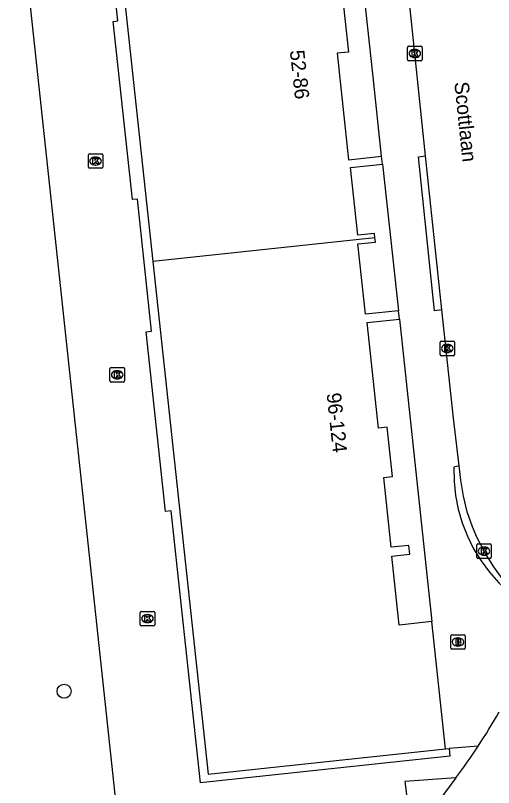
# Model space of a CAD drawing. Extents: x 161253 to 161848, y 384872 to 385383.
# Drawn here: x 161322.6 to 161355.7, y 384938.3 to 384991.8 of the extents above; entities that cross this region are included whole.
import ezdxf

# ---------------------------------------------------------------- set-up
doc = ezdxf.new("R2010")
doc.units = 0
for name, color, linetype in [('IMGEO_Boom', 7, 'Continuous'), ('IMGEO_Brandkraan', 7, 'Continuous'), ('IMGEO_Fietspad_gesloten', 7, 'Continuous'), ('IMGEO_Kolk', 7, 'Continuous'), ('IMGEO_Openbare_ruimte_label', 7, 'Continuous'), ('IMGEO_Pand', 7, 'Continuous'), ('IMGEO_Pand_nummerreeks', 7, 'Continuous'), ('IMGEO_Rijbaan_lokaal_open', 7, 'Continuous'), ('IMGEO_Voetpad_open', 7, 'Continuous')]:
    doc.layers.add(name, color=color, linetype=linetype)

msp = doc.modelspace()

# ---------------------------------------------------------------- linework, layer by layer
at = {"layer": 'IMGEO_Boom'}
msp.add_circle((161325.944, 384945.018), 0.489, dxfattribs=at)
at = {"layer": 'IMGEO_Brandkraan'}
for p, q in [((161352.707, 384948), (161352.707, 384948.852)), ((161352.782, 384948.926), (161353.634, 384948.926)), ((161353.708, 384948.852), (161353.708, 384948)), ((161353.195, 384948.706), (161353.22, 384948.706)), ((161353.634, 384947.926), (161352.782, 384947.926)), ((161353.218, 384948.146), (161353.193, 384948.146))]:
    msp.add_line(p, q, dxfattribs=at)
for points in [[(161352.707, 384948), (161352.707, 384948.852)], [(161352.782, 384948.926), (161353.634, 384948.926)], [(161353.708, 384948.852), (161353.708, 384948)], [(161353.055, 384948.626), (161353.055, 384948.226), (161353.268, 384948.226)], [(161353.286, 384948.626), (161353.055, 384948.626)], [(161353.234, 384948.545), (161353.18, 384948.545), (161353.18, 384948.469)], [(161353.18, 384948.469), (161353.233, 384948.469)], [(161353.242, 384948.393), (161353.18, 384948.393), (161353.18, 384948.312)], [(161353.18, 384948.312), (161353.242, 384948.312)], [(161353.634, 384947.926), (161352.782, 384947.926)]]:
    msp.add_lwpolyline(points, dxfattribs=at)
for centre, radius, start, end in [((161352.784, 384948.85), 0.0765, 91.552, 178.448), ((161352.784, 384948.85), 0.0765, 91.552, 178.448), ((161353.632, 384948.85), 0.0765, 1.552, 88.448), ((161353.632, 384948.85), 0.0765, 1.552, 88.448), ((161353.235, 384948.507), 0.0379, 267.8285, 90.9355), ((161353.243, 384948.352), 0.0404, 269.8759, 90.5077), ((161353.274, 384948.477), 0.251, 268.6676, 293.5347), ((161353.29, 384948.481), 0.145, 59.4692, 91.5367), ((161353.315, 384948.528), 0.0922, 285.5137, 58.1501), ((161353.32, 384948.336), 0.105, 301.3115, 78.989), ((161352.784, 384948.002), 0.0765, 181.552, 268.448), ((161352.784, 384948.002), 0.0765, 181.552, 268.448), ((161353.632, 384948.002), 0.0765, 271.552, 358.448), ((161353.632, 384948.002), 0.0765, 271.552, 358.448)]:
    msp.add_arc(centre, radius, start, end, dxfattribs=at)
for centre, major_axis, ratio, start_param, end_param in [((161353.194, 384948.426), (-0.387, 0.002), 0.722429, 4.712389, 7.853982), ((161353.219, 384948.426), (-0.39, 0.002), 0.717154, 1.570796, 4.712389)]:
    msp.add_ellipse(centre, major_axis=major_axis, ratio=ratio, start_param=start_param, end_param=end_param, dxfattribs=at)
at = {"layer": 'IMGEO_Fietspad_gesloten'}
msp.add_lwpolyline([(161353.067, 384939.032), (161352.732, 384938.592), (161341.413, 384923.282)], dxfattribs=at)
msp.add_arc((161318.363, 384965.194), 43.457, 326.5147, 330.1784, dxfattribs=at)
at = {"layer": 'IMGEO_Kolk'}
for p, q in [((161349.718, 384988.745), (161349.718, 384989.597)), ((161349.793, 384989.671), (161350.645, 384989.671)), ((161350.206, 384989.451), (161350.231, 384989.451)), ((161350.719, 384989.597), (161350.719, 384988.745)), ((161350.229, 384988.891), (161350.204, 384988.891)), ((161350.645, 384988.671), (161349.793, 384988.671)), ((161327.62, 384981.296), (161327.62, 384982.148)), ((161327.695, 384982.222), (161328.547, 384982.222)), ((161328.108, 384982.002), (161328.133, 384982.002)), ((161328.621, 384982.148), (161328.621, 384981.296)), ((161328.131, 384981.442), (161328.106, 384981.442)), ((161328.547, 384981.222), (161327.695, 384981.222)), ((161351.968, 384968.323), (161351.968, 384969.175)), ((161352.043, 384969.249), (161352.895, 384969.249)), ((161352.969, 384969.175), (161352.969, 384968.323)), ((161352.456, 384969.029), (161352.481, 384969.029)), ((161352.895, 384968.249), (161352.043, 384968.249)), ((161352.479, 384968.469), (161352.454, 384968.469)), ((161329.119, 384966.5), (161329.119, 384967.352)), ((161329.194, 384967.426), (161330.046, 384967.426)), ((161329.607, 384967.206), (161329.632, 384967.206)), ((161330.12, 384967.352), (161330.12, 384966.5)), ((161330.046, 384966.426), (161329.194, 384966.426)), ((161329.63, 384966.646), (161329.605, 384966.646)), ((161354.51, 384954.293), (161354.51, 384955.145)), ((161354.585, 384955.219), (161355.437, 384955.219)), ((161355.511, 384955.145), (161355.511, 384954.293)), ((161354.998, 384954.999), (161355.023, 384954.999)), ((161355.437, 384954.219), (161354.585, 384954.219)), ((161355.021, 384954.439), (161354.996, 384954.439)), ((161331.213, 384949.622), (161331.213, 384950.474)), ((161331.288, 384950.548), (161332.14, 384950.548)), ((161332.214, 384950.474), (161332.214, 384949.622)), ((161331.701, 384950.328), (161331.726, 384950.328)), ((161332.14, 384949.548), (161331.288, 384949.548)), ((161331.724, 384949.768), (161331.699, 384949.768))]:
    msp.add_line(p, q, dxfattribs=at)
for points in [[(161349.718, 384988.745), (161349.718, 384989.597)], [(161349.793, 384989.671), (161350.645, 384989.671)], [(161350.039, 384989.371), (161350.162, 384989.371), (161350.162, 384989.22), (161350.292, 384989.371), (161350.456, 384989.371), (161350.31, 384989.22), (161350.463, 384988.971), (161350.311, 384988.971), (161350.226, 384989.135), (161350.162, 384989.068), (161350.162, 384988.971), (161350.039, 384988.971), (161350.039, 384989.371)], [(161350.719, 384989.597), (161350.719, 384988.745)], [(161350.645, 384988.671), (161349.793, 384988.671)], [(161327.62, 384981.296), (161327.62, 384982.148)], [(161327.695, 384982.222), (161328.547, 384982.222)], [(161327.941, 384981.922), (161328.064, 384981.922), (161328.064, 384981.771), (161328.194, 384981.922), (161328.358, 384981.922), (161328.212, 384981.771), (161328.365, 384981.522), (161328.213, 384981.522), (161328.128, 384981.686), (161328.064, 384981.619), (161328.064, 384981.522), (161327.941, 384981.522), (161327.941, 384981.922)], [(161328.621, 384982.148), (161328.621, 384981.296)], [(161328.547, 384981.222), (161327.695, 384981.222)], [(161351.968, 384968.323), (161351.968, 384969.175)], [(161352.043, 384969.249), (161352.895, 384969.249)], [(161352.969, 384969.175), (161352.969, 384968.323)], [(161352.289, 384968.949), (161352.412, 384968.949), (161352.412, 384968.798), (161352.542, 384968.949), (161352.706, 384968.949), (161352.56, 384968.798), (161352.713, 384968.549), (161352.561, 384968.549), (161352.476, 384968.713), (161352.412, 384968.646), (161352.412, 384968.549), (161352.289, 384968.549), (161352.289, 384968.949)], [(161352.895, 384968.249), (161352.043, 384968.249)], [(161329.119, 384966.5), (161329.119, 384967.352)], [(161329.194, 384967.426), (161330.046, 384967.426)], [(161329.44, 384967.126), (161329.563, 384967.126), (161329.563, 384966.975), (161329.693, 384967.126), (161329.857, 384967.126), (161329.711, 384966.975), (161329.864, 384966.726), (161329.712, 384966.726), (161329.627, 384966.89), (161329.563, 384966.823), (161329.563, 384966.726), (161329.44, 384966.726), (161329.44, 384967.126)], [(161330.12, 384967.352), (161330.12, 384966.5)], [(161330.046, 384966.426), (161329.194, 384966.426)], [(161354.51, 384954.293), (161354.51, 384955.145)], [(161354.585, 384955.219), (161355.437, 384955.219)], [(161355.511, 384955.145), (161355.511, 384954.293)], [(161354.831, 384954.919), (161354.954, 384954.919), (161354.954, 384954.768), (161355.084, 384954.919), (161355.248, 384954.919), (161355.102, 384954.768), (161355.255, 384954.519), (161355.103, 384954.519), (161355.018, 384954.683), (161354.954, 384954.616), (161354.954, 384954.519), (161354.831, 384954.519), (161354.831, 384954.919)], [(161355.437, 384954.219), (161354.585, 384954.219)], [(161331.213, 384949.622), (161331.213, 384950.474)], [(161331.288, 384950.548), (161332.14, 384950.548)], [(161332.214, 384950.474), (161332.214, 384949.622)], [(161331.534, 384950.248), (161331.657, 384950.248), (161331.657, 384950.097), (161331.787, 384950.248), (161331.951, 384950.248), (161331.805, 384950.097), (161331.958, 384949.848), (161331.806, 384949.848), (161331.721, 384950.012), (161331.657, 384949.945), (161331.657, 384949.848), (161331.534, 384949.848), (161331.534, 384950.248)], [(161332.14, 384949.548), (161331.288, 384949.548)]]:
    msp.add_lwpolyline(points, dxfattribs=at)
for centre, start, end in [((161349.795, 384989.595), 91.552, 178.448), ((161349.795, 384989.595), 91.552, 178.448), ((161350.643, 384989.595), 1.552, 88.448), ((161350.643, 384989.595), 1.552, 88.448), ((161349.795, 384988.747), 181.552, 268.448), ((161349.795, 384988.747), 181.552, 268.448), ((161350.643, 384988.747), 271.552, 358.448), ((161350.643, 384988.747), 271.552, 358.448), ((161327.697, 384982.146), 91.552, 178.448), ((161327.697, 384982.146), 91.552, 178.448), ((161328.545, 384982.146), 1.552, 88.448), ((161328.545, 384982.146), 1.552, 88.448), ((161327.697, 384981.298), 181.552, 268.448), ((161327.697, 384981.298), 181.552, 268.448), ((161328.545, 384981.298), 271.552, 358.448), ((161328.545, 384981.298), 271.552, 358.448), ((161352.045, 384969.173), 91.552, 178.448), ((161352.045, 384969.173), 91.552, 178.448), ((161352.893, 384969.173), 1.552, 88.448), ((161352.893, 384969.173), 1.552, 88.448), ((161352.045, 384968.325), 181.552, 268.448), ((161352.045, 384968.325), 181.552, 268.448), ((161352.893, 384968.325), 271.552, 358.448), ((161352.893, 384968.325), 271.552, 358.448), ((161329.196, 384967.35), 91.552, 178.448), ((161329.196, 384967.35), 91.552, 178.448), ((161330.044, 384967.35), 1.552, 88.448), ((161330.044, 384967.35), 1.552, 88.448), ((161329.196, 384966.502), 181.552, 268.448), ((161329.196, 384966.502), 181.552, 268.448), ((161330.044, 384966.502), 271.552, 358.448), ((161330.044, 384966.502), 271.552, 358.448), ((161354.587, 384955.143), 91.552, 178.448), ((161354.587, 384955.143), 91.552, 178.448), ((161355.435, 384955.143), 1.552, 88.448), ((161355.435, 384955.143), 1.552, 88.448), ((161354.587, 384954.295), 181.552, 268.448), ((161354.587, 384954.295), 181.552, 268.448), ((161355.435, 384954.295), 271.552, 358.448), ((161355.435, 384954.295), 271.552, 358.448), ((161331.29, 384950.472), 91.552, 178.448), ((161331.29, 384950.472), 91.552, 178.448), ((161332.138, 384950.472), 1.552, 88.448), ((161332.138, 384950.472), 1.552, 88.448), ((161331.29, 384949.624), 181.552, 268.448), ((161331.29, 384949.624), 181.552, 268.448), ((161332.138, 384949.624), 271.552, 358.448), ((161332.138, 384949.624), 271.552, 358.448)]:
    msp.add_arc(centre, 0.0765, start, end, dxfattribs=at)
for centre, major_axis, ratio, start_param, end_param in [((161350.205, 384989.171), (-0.387, 0.002), 0.722429, 4.712389, 7.853982), ((161350.23, 384989.171), (-0.39, 0.002), 0.717154, 1.570796, 4.712389), ((161328.107, 384981.722), (-0.387, 0.002), 0.722429, 4.712389, 7.853982), ((161328.132, 384981.722), (-0.39, 0.002), 0.717154, 1.570796, 4.712389), ((161352.455, 384968.749), (-0.387, 0.002), 0.722429, 4.712389, 7.853982), ((161352.48, 384968.749), (-0.39, 0.002), 0.717154, 1.570796, 4.712389), ((161329.606, 384966.926), (-0.387, 0.002), 0.722429, 4.712389, 7.853982), ((161329.631, 384966.926), (-0.39, 0.002), 0.717154, 1.570796, 4.712389), ((161354.997, 384954.719), (-0.387, 0.002), 0.722429, 4.712389, 7.853982), ((161355.022, 384954.719), (-0.39, 0.002), 0.717154, 1.570796, 4.712389), ((161331.7, 384950.048), (-0.387, 0.002), 0.722429, 4.712389, 7.853982), ((161331.725, 384950.048), (-0.39, 0.002), 0.717154, 1.570796, 4.712389)]:
    msp.add_ellipse(centre, major_axis=major_axis, ratio=ratio, start_param=start_param, end_param=end_param, dxfattribs=at)
at = {"layer": 'IMGEO_Pand'}
for points in [[(161345.188, 384997.822), (161345.22, 384997.527), (161343.986, 384997.395), (161344.504, 384992.575), (161345.261, 384992.657), (161345.626, 384989.268), (161344.847, 384989.184), (161345.639, 384981.819), (161347.916, 384982.064)], [(161329.788, 384996.166), (161332.09, 384974.761)], [(161347.976, 384981.513), (161347.916, 384982.064)], [(161347.464, 384976.414), (161347.432, 384976.709), (161346.267, 384976.583), (161345.763, 384981.275), (161347.976, 384981.513)], [(161347.464, 384976.414), (161332.09, 384974.761)], [(161349.099, 384971.364), (161346.806, 384971.118), (161346.282, 384975.989), (161347.495, 384976.119), (161347.464, 384976.414)], [(161332.09, 384974.761), (161335.907, 384939.267), (161352.34, 384941.034)], [(161349.162, 384970.781), (161349.099, 384971.364)], [(161351.394, 384949.836), (161349.145, 384949.594), (161348.631, 384954.373), (161349.881, 384954.507), (161349.815, 384955.119), (161348.591, 384954.987), (161348.072, 384959.82), (161348.677, 384959.885), (161348.309, 384963.303), (161347.699, 384963.238), (161346.913, 384970.539), (161349.162, 384970.781)], [(161352.34, 384941.034), (161351.394, 384949.836)]]:
    msp.add_lwpolyline(points, dxfattribs=at)
at = {"layer": 'IMGEO_Rijbaan_lokaal_open'}
for points in [[(161352.588, 384941.054), (161352.645, 384940.528), (161335.385, 384938.672), (161333.36, 384957.504), (161332.965, 384957.461), (161331.628, 384969.898), (161332.002, 384969.938), (161331.017, 384979.097), (161330.667, 384979.059), (161329.341, 384991.388), (161329.661, 384991.422), (161328.734, 385000), (161328.683, 385000.47), (161328.371, 385000.44), (161327.034, 385012.879), (161327.381, 385012.916), (161326.219, 385023.721), (161335.826, 385024.754)], [(161353.067, 384939.032), (161349.538, 384938.768), (161349.844, 384936.245), (161348.022, 384934.003), (161333.73, 384932.332), (161329.539, 384937.213), (161322.803, 385000), (161320.382, 385022.568), (161319.802, 385024.058)], [(161350.964, 384982.082), (161349.825, 384992.946)], [(161352.083, 384971.42), (161350.964, 384982.082)], [(161353.293, 384960.634), (161352.903, 384963.923), (161352.083, 384971.42)], [(161356.682, 384952.243), (161355.7, 384953.619), (161355.059, 384954.63), (161354.511, 384955.694), (161354.209, 384956.395), (161353.847, 384957.448), (161353.581, 384958.529), (161353.412, 384959.629), (161353.293, 384960.634)], [(161354.608, 384941.218), (161352.588, 384941.054)]]:
    msp.add_lwpolyline(points, dxfattribs=at)
msp.add_arc((161318.717, 384964.883), 42.99, 323.0359, 326.601, dxfattribs=at)
at = {"layer": 'IMGEO_Voetpad_open'}
for points in [[(161347.916, 384982.064), (161347.327, 384987.554), (161346.825, 384992.221), (161345.635, 385003.548), (161345.12, 385008.375)], [(161352.083, 384971.42), (161351.587, 384971.365), (161350.468, 384982.027), (161350.964, 384982.082)], [(161347.976, 384981.513), (161349.099, 384971.364)], [(161349.162, 384970.781), (161351.394, 384949.836)], [(161353.293, 384960.634), (161352.919, 384960.53), (161352.934, 384959.55), (161353.036, 384958.575), (161353.225, 384957.613), (161353.499, 384956.672), (161353.856, 384955.759), (161354.294, 384954.881), (161354.808, 384954.047), (161355.394, 384953.261), (161356.048, 384952.531), (161356.523, 384952.075), (161356.682, 384952.243)], [(161352.34, 384941.034), (161352.588, 384941.054)]]:
    msp.add_lwpolyline(points, dxfattribs=at)

# ---------------------------------------------------------------- texts
at = {"layer": 'IMGEO_Openbare_ruimte_label'}
msp.add_text('Scottlaan', height=1, rotation=275.967, dxfattribs=at).set_placement((161352.949, 384987.167))
at = {"layer": 'IMGEO_Pand_nummerreeks'}
for s, rotation, p in [('52-86', 276.2547, (161341.567, 384989.361)), ('96-124', 276.1905, (161344.107, 384965.625))]:
    msp.add_text(s, height=1, rotation=rotation, dxfattribs=at).set_placement(p)

doc.saveas('drawing.dxf')
